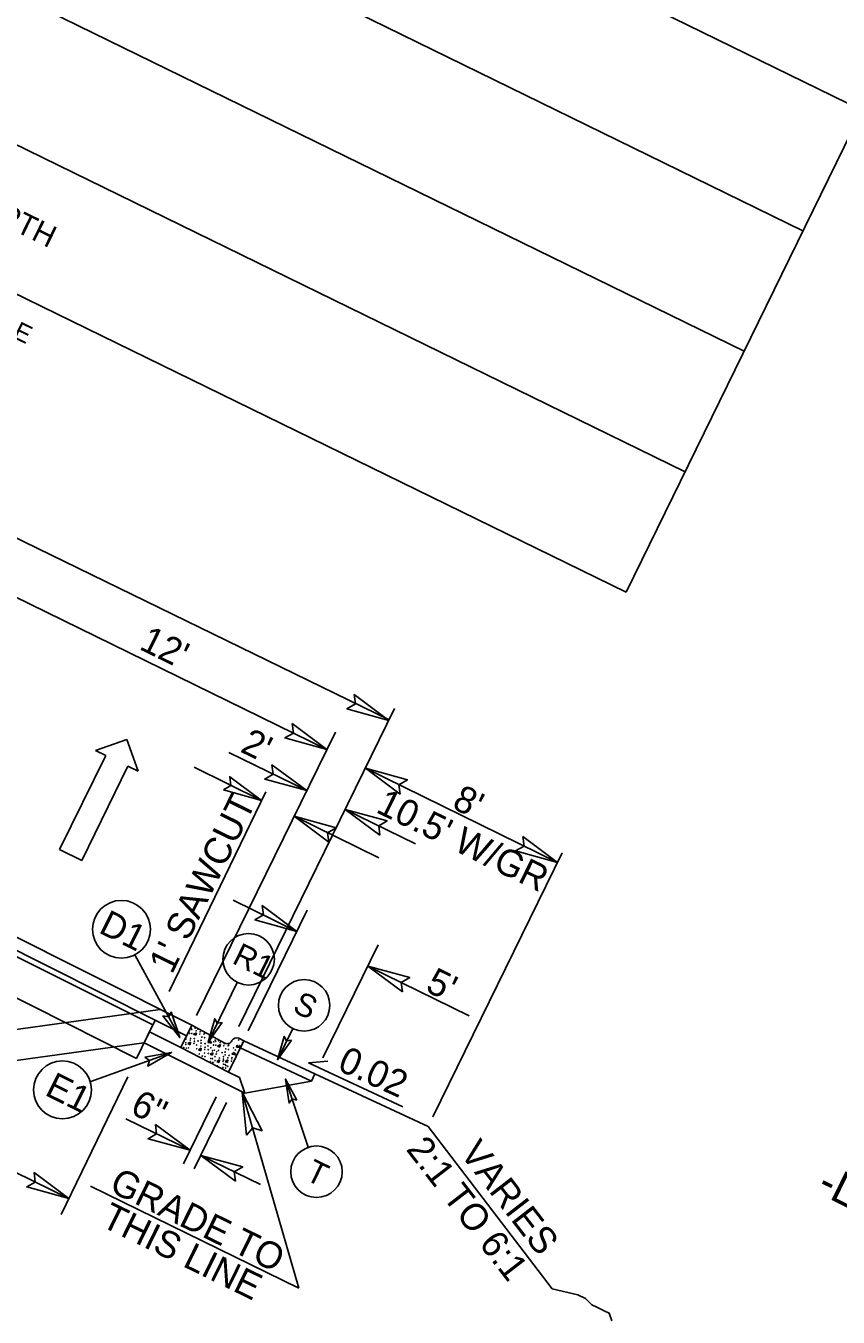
# Model space of a CAD drawing. Extents: x 1518247 to 1523638, y 635234 to 639927.
# Drawn here: x 1521902.2 to 1522204.9, y 638576.7 to 639057.9 of the extents above; entities that cross this region are included whole.
import ezdxf

# ---------------------------------------------------------------- set-up
doc = ezdxf.new("R2010")
doc.units = 0
for name, color, linetype in [('DTM TIN Hull White', 7, 'Continuous'), ('Old_Level_21', 7, 'Continuous'), ('Prop Dimension', 7, 'Continuous'), ('Prop Lane Arrow CELL', 7, 'Continuous'), ('Prop Shade Light', 7, 'Continuous'), ('Sheet Typical CELL', 7, 'Continuous'), ('Typical Arrow Superelevation CELL', 7, 'Continuous'), ('Typical Berm CELL', 7, 'Continuous'), ('Typical Berm Information CELL', 7, 'Continuous'), ('Typical Curb CELL', 7, 'Continuous'), ('Typical Hinge Slope Arterial CELL', 7, 'Continuous'), ('Typical Hinge Slope Interstate CELL', 7, 'Continuous'), ('Typical ID Circle CELL', 7, 'Continuous'), ('Typical Pavement Slope CELL', 7, 'Continuous'), ('Typical Text General CELL', 7, 'Continuous'), ('Typical Text ID Circle CELL', 7, 'Continuous')]:
    doc.layers.add(name, color=color, linetype=linetype)

# ---------------------------------------------------------------- blocks, each defined once
blk = doc.blocks.new('TERMINATOR')
at = {"layer": 'Prop Shade Light'}
blk.add_lwpolyline([(-0.469, 0.081), (0, 0), (-0.471, -0.083), (-0.411, 0)], close=True, dxfattribs=at)

msp = doc.modelspace()

# ---------------------------------------------------------------- linework, layer by layer
at = {"layer": 'DTM TIN Hull White'}
for p, q in [((1521949.57, 638685.65), (1521767.55, 638776.75)), ((1521943.46, 638673.16), (1521761.27, 638764.74)), ((1521949.57, 638685.65), (1521943.46, 638673.16))]:
    msp.add_line(p, q, dxfattribs=at)
at = {"layer": 'Prop Dimension'}
for p, q in [((1522037.58, 638799.28), (1521619.64, 639003.32)), ((1521819.91, 638883.5), (1522014.4, 638788.21)), ((1521981.59, 638685.01), (1522039.67, 638803.53)), ((1521918.24, 638620.97), (1521552.58, 638799.48)), ((1521965.84, 638689.11), (1522017.62, 638794.78)), ((1521977.9, 638787.19), (1522006.91, 638772.98)), ((1521964.93, 638781.64), (1521990.11, 638769.3)), ((1522028.76, 638781.27), (1522100.35, 638746.19)), ((1521955.64, 638698.1), (1521991.67, 638772.52)), ((1522002.22, 638763.37), (1522033.82, 638747.89)), ((1522021.23, 638765.96), (1522047.38, 638753.15)), ((1522053.91, 638651.42), (1522102.1, 638749.77)), ((1521979.52, 638732.12), (1522003.25, 638720.49)), ((1521985.11, 638683.47), (1522007.12, 638728.37)), ((1522012.86, 638673.35), (1522033.49, 638715.45)), ((1522029.63, 638707.57), (1522067.44, 638689.04)), ((1521952.32, 638691.4), (1521882.21, 638681.7)), ((1521946.26, 638678.93), (1521876.19, 638669.24)), ((1521915.38, 638614.96), (1521940.23, 638666.29)), ((1522004.01, 638587.52), (1521982.89, 638660.63)), ((1521973.18, 638658.79), (1521960.98, 638633.88)), ((1521977.05, 638656.67), (1521964.98, 638632.03)), ((1521939.47, 638650.69), (1521963.46, 638638.94)), ((1521967.41, 638637), (1521989.64, 638626.11)), ((1521926.38, 638625.56), (1522004.01, 638587.52))]:
    msp.add_line(p, q, dxfattribs=at)
at = {"layer": 'Prop Lane Arrow CELL'}
for p, q in [((1521928.25, 638787.93), (1521939.89, 638792.02)), ((1521939.89, 638792.02), (1521944.05, 638780.19)), ((1521914.82, 638751), (1521932.01, 638786.09)), ((1521932.01, 638786.09), (1521928.25, 638787.93)), ((1521940.29, 638782.04), (1521923.09, 638746.94)), ((1521944.05, 638780.19), (1521940.29, 638782.04)), ((1521923.09, 638746.94), (1521914.82, 638751))]:
    msp.add_line(p, q, dxfattribs=at)
at = {"layer": 'Prop Shade Light'}
for points in [[(1521956.41, 638690.56), (1521959.59, 638680.94), (1521953.3, 638688.97), (1521955.47, 638688.68)], [(1521975.41, 638686.54), (1521970.13, 638679.24), (1521972.64, 638687.95), (1521973.56, 638686.24)], [(1522001.27, 638679.97), (1521996, 638672.67), (1521998.51, 638681.38), (1521999.42, 638679.67)], [(1521946.55, 638673.62), (1521956.53, 638675.36), (1521947.67, 638670.31), (1521948.27, 638672.41)], [(1522003.26, 638657.54), (1521999, 638665.48), (1522000.33, 638656.51), (1522001.47, 638658.08)]]:
    msp.add_lwpolyline(points, close=True, dxfattribs=at)
at = {"layer": 'Sheet Typical CELL'}
for p, q in [((1522125.92, 638846.87), (1522393.92, 639394.84)), ((1521704.98, 639275.38), (1522213.79, 639026.53)), ((1521683.02, 639230.46), (1522191.82, 638981.61)), ((1521661.05, 639185.55), (1522169.86, 638936.7)), ((1521639.08, 639140.63), (1522147.89, 638891.78)), ((1521617.12, 639095.71), (1522125.92, 638846.87)), ((1522008.69, 638664.72), (1521982.13, 638677.05))]:
    msp.add_line(p, q, dxfattribs=at)
at = {"layer": 'Typical Arrow Superelevation CELL'}
msp.add_line((1522007.51, 638671.46), (1522014.77, 638672.1), dxfattribs=at)
at = {"layer": 'Typical Berm CELL'}
msp.add_line((1522052.16, 638647.84), (1521983.45, 638679.75), dxfattribs=at)
at = {"layer": 'Typical Berm Information CELL'}
msp.add_line((1522007.51, 638671.46), (1522042.73, 638655.1), dxfattribs=at)
at = {"layer": 'Typical Curb CELL'}
for p, q in [((1521960, 638677.18), (1521964.09, 638685.53)), ((1521964.09, 638685.53), (1521976.37, 638678.87)), ((1521964.75, 638682.16), (1521965.79, 638682.71)), ((1521965.64, 638681.78), (1521964.75, 638682.16)), ((1521965.79, 638682.71), (1521965.64, 638681.78)), ((1521970.05, 638679.11), (1521970.9, 638679.71)), ((1521970.9, 638679.71), (1521971.38, 638678.81)), ((1521977.72, 638668.05), (1521983.45, 638679.75)), ((1521979, 638679.71), (1521979.03, 638679.78)), ((1521983.45, 638679.75), (1521981.59, 638680.66)), ((1521977.72, 638668.05), (1521960, 638677.18)), ((1521962.57, 638678.65), (1521963.61, 638679.2)), ((1521963.46, 638678.27), (1521962.57, 638678.65)), ((1521963.61, 638679.2), (1521963.46, 638678.27)), ((1521966.55, 638676.4), (1521967.59, 638676.96)), ((1521967.44, 638676.03), (1521966.55, 638676.4)), ((1521967.59, 638676.96), (1521967.44, 638676.03)), ((1521971.38, 638678.81), (1521970.05, 638679.11)), ((1521970.88, 638674.7), (1521971.92, 638675.25)), ((1521971.92, 638675.25), (1521971.76, 638674.32)), ((1521973.7, 638677.77), (1521974.73, 638678.33)), ((1521974.58, 638677.4), (1521973.7, 638677.77)), ((1521974.73, 638678.33), (1521974.58, 638677.4)), ((1521978.99, 638674.72), (1521979.84, 638675.33)), ((1521979.84, 638675.33), (1521980.32, 638674.43)), ((1521980.92, 638678.03), (1521980.72, 638677.32)), ((1521980.72, 638677.32), (1521981.87, 638677.17)), ((1521981.87, 638677.17), (1521980.92, 638678.03)), ((1521971.76, 638674.32), (1521970.88, 638674.7)), ((1521973.39, 638672.01), (1521974.43, 638672.57)), ((1521974.28, 638671.63), (1521973.39, 638672.01)), ((1521974.43, 638672.57), (1521974.28, 638671.63)), ((1521976.53, 638672.05), (1521977.57, 638672.61)), ((1521977.42, 638671.68), (1521976.53, 638672.05)), ((1521977.57, 638672.61), (1521977.42, 638671.68)), ((1521980.32, 638674.43), (1521978.99, 638674.72))]:
    msp.add_line(p, q, dxfattribs=at)
for centre in [(1521965.3, 638684.42), (1521961.91, 638680.39), (1521962.22, 638681.52), (1521963.25, 638682.49), (1521963.35, 638683.71), (1521963.52, 638679.96), (1521963.65, 638680.62), (1521963.81, 638684.35), (1521964.09, 638683.91), (1521964.1, 638682.48), (1521965.03, 638680.55), (1521965.7, 638683.47), (1521966.38, 638684.04), (1521966.42, 638679.67), (1521967.07, 638682.24), (1521967.23, 638683.07), (1521967.54, 638679.88), (1521967.84, 638681.1), (1521968.64, 638682.23), (1521968.84, 638680.87), (1521968.94, 638682.53), (1521970.68, 638681.43), (1521971.36, 638680.64), (1521972.75, 638679.96), (1521974.1, 638679.73), (1521981.54, 638680.01), (1521961.06, 638677.22), (1521961.87, 638678.35), (1521961.92, 638678.97), (1521962.06, 638676.98), (1521962.85, 638677.04), (1521964.9, 638678.73), (1521965.05, 638679.56), (1521965.89, 638678.15), (1521965.9, 638676.73), (1521966.83, 638674.8), (1521967.5, 638677.72), (1521967.55, 638678.86), (1521968.8, 638675.16), (1521968.88, 638676.49), (1521969.04, 638678.69), (1521969.03, 638677.31), (1521970.12, 638677.8), (1521970.22, 638676.45), (1521970.23, 638675.02), (1521971.17, 638677.14), (1521971.83, 638676.01), (1521972.2, 638678.11), (1521972.29, 638679.33), (1521972.59, 638676.24), (1521973.03, 638679.52), (1521973.05, 638678.1), (1521973.36, 638675.61), (1521973.98, 638676.17), (1521974.64, 638679.09), (1521975.37, 638675.29), (1521976.02, 638677.86), (1521976.17, 638678.68), (1521976.49, 638675.5), (1521976.78, 638676.72), (1521977.59, 638677.85), (1521977.78, 638676.48), (1521977.89, 638678.15), (1521979.63, 638677.04), (1521980.31, 638676.26), (1521981.96, 638677.88), (1521982.97, 638679), (1521967.99, 638674.03), (1521968.99, 638673.8), (1521970.95, 638671.92), (1521971.16, 638673.1), (1521971.76, 638673.04), (1521971.95, 638671.68), (1521972.73, 638673.76), (1521972.74, 638672.33), (1521973.2, 638674.78), (1521973.67, 638670.41), (1521974.34, 638673.32), (1521975.72, 638672.09), (1521975.87, 638673.8), (1521975.87, 638672.92), (1521975.88, 638672.38), (1521975.91, 638670.98), (1521976.5, 638674.48), (1521976.51, 638670.93), (1521976.82, 638670.45), (1521977.48, 638673.37), (1521977.49, 638670.22), (1521977.98, 638674.31), (1521978.86, 638672.14), (1521979.01, 638672.96), (1521979.07, 638673.42), (1521975.7, 638669.8), (1521976.7, 638669.56)]:
    msp.add_circle(centre, 0.064, dxfattribs=at)
for centre, start, end in [((1521977.28, 638680.55), 241.5117, 333.8962), ((1521980.75, 638678.94), 63.8962, 153.8962)]:
    msp.add_arc(centre, 1.91, start, end, dxfattribs=at)
at = {"layer": 'Typical Hinge Slope Interstate CELL'}
for p, q in [((1522009.98, 638667.43), (1522008.69, 638664.72)), ((1522052.16, 638647.84), (1522098.38, 638587.23))]:
    msp.add_line(p, q, dxfattribs=at)
msp.add_lwpolyline([(1522098.38, 638587.23), (1522107.98, 638585.02), (1522110.77, 638583.66), (1522113.1, 638581.37), (1522114.95, 638580.46), (1522117.74, 638579.09), (1522119.6, 638578.18), (1522120.54, 638575.41)], dxfattribs=at)
at = {"layer": 'Typical ID Circle CELL'}
for p, q in [((1521959.24, 638681.65), (1521942.86, 638711.7)), ((1521981.03, 638701.49), (1521970.13, 638679.24)), ((1522001.7, 638684.32), (1521996, 638672.67)), ((1521926.5, 638664.56), (1521956.55, 638675.35)), ((1522007.49, 638640.02), (1521999, 638665.48))]:
    msp.add_line(p, q, dxfattribs=at)
for centre, radius in [((1521937.87, 638721.26), 10.78), ((1521985.25, 638710.1), 9.59), ((1522005.92, 638692.93), 9.59), ((1521915.89, 638661.42), 10.78), ((1522010.53, 638630.93), 9.59)]:
    msp.add_circle(centre, radius, dxfattribs=at)
at = {"layer": 'Typical Pavement Slope CELL'}
for p, q in [((1521770.4, 638782.47), (1521964.09, 638685.53)), ((1521950.42, 638687.37), (1521768.58, 638778.92)), ((1521950.42, 638687.37), (1521946.3, 638678.94)), ((1521962.07, 638681.54), (1521950.42, 638687.37)), ((1521960, 638677.18), (1521948.34, 638683.01)), ((1521983.82, 638660.16), (1521946.3, 638678.94)), ((1521977.72, 638668.05), (1521981.81, 638666.04)), ((1521981.81, 638666.04), (1521983.82, 638660.16)), ((1521983.82, 638660.16), (1522008.69, 638664.72))]:
    msp.add_line(p, q, dxfattribs=at)

# ---------------------------------------------------------------- block references
at = {"layer": 'Prop Dimension'}
for p, xscale, yscale, rotation in [((1522037.51, 638799.13), 33.82820784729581, 36.4155251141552, -26.103820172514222), ((1522014.44, 638788.29), 33.82820784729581, 36.4155251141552, -26.103820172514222), ((1522006.91, 638772.98), 33.82820784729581, 36.4155251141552, -26.103820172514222), ((1522028.76, 638781.27), 33.82820784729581, 36.4155251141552, 153.89617982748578), ((1521990.11, 638769.3), 30.938856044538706, -33.30518407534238, -25.836011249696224), ((1522021.23, 638765.96), 33.82820784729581, 36.4155251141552, 153.89617982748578), ((1522002.22, 638763.37), 33.82820784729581, 36.4155251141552, 153.89617982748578), ((1522100.35, 638746.19), 33.82820784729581, 36.4155251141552, -26.103820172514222), ((1522003.25, 638720.49), 33.82820784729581, 36.4155251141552, -26.103820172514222), ((1522029.63, 638707.57), 33.82820784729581, 36.4155251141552, 153.89617982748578), ((1521982.89, 638660.63), 33.828207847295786, 36.415525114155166, 106.22234335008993), ((1521963.46, 638638.94), 33.82820784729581, 36.4155251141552, -26.103820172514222), ((1521967.41, 638637), 33.82820784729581, 36.4155251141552, 153.89617982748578), ((1521918.24, 638620.97), 33.82820784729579, 36.41552511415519, -26.103820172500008)]:
    msp.add_blockref('TERMINATOR', p, dxfattribs=dict(at, xscale=xscale, yscale=yscale, rotation=rotation))

# ---------------------------------------------------------------- texts
at = {"layer": 'Old_Level_21'}
msp.add_text('NOTE:  PAVEMENT EDGE SLOPES ARE 1:1 UNLESS SHOWN OTHERWISE', height=6.75, rotation=333.8298, dxfattribs=at).set_placement((1521617.01, 639079.5))
at = {"layer": 'Prop Dimension'}
for s, height, rotation, p in [("12'", 9.969, 333.8962, (1521944.1, 638825.83)), ("2'", 9.969, 333.9793, (1521981.76, 638787.61)), ("1' SAWCUT", 10, 63.9377, (1521956.69, 638704.2)), ("10.5' W/GR", 9.969, 333.8962, (1522032.27, 638765.07)), ("8'", 9.969, 333.8962, (1522060.61, 638766.59)), ("5'", 9.969, 333.9793, (1522050.7, 638698.41)), ('6"', 9.969, 333.8962, (1521940.68, 638652.91))]:
    msp.add_text(s, height=height, rotation=rotation, dxfattribs=at).set_placement(p)
at = {"layer": 'Sheet Typical CELL'}
msp.add_text('MILLING BITUMINOUS PAVEMENT. 1 1/2" DEPTH', height=8.1788, rotation=333.8298, dxfattribs=at).set_placement((1521683.86, 639086.68))
at = {"layer": 'Typical Berm Information CELL'}
msp.add_text('0.02', height=9.969, rotation=335.7046, dxfattribs=at).set_placement((1522017.92, 638668.95))
at = {"layer": 'Typical Hinge Slope Arterial CELL'}
for s, p in [('2:1 TO 6:1', (1522043.65, 638639.21)), ('VARIES', (1522063.66, 638637.77))]:
    msp.add_text(s, height=9.969, rotation=307.6683, dxfattribs=at).set_placement(p)
at = {"layer": 'Typical Pavement Slope CELL'}
msp.add_text('-L- STA. 25+35.00 to -L- STA. 25+85.00', height=11.8983, rotation=333.8962, dxfattribs=at).set_placement((1522196.49, 638623.31))
at = {"layer": 'Typical Text General CELL'}
for s, p in [('GRADE TO', (1521932.87, 638623.86)), ('THIS LINE', (1521929.73, 638610.85))]:
    msp.add_text(s, height=9.969, rotation=333.8962, dxfattribs=at).set_placement(p)
at = {"layer": 'Typical Text ID Circle CELL'}
for s, height, rotation, p in [('D1', 9.65, 333.6189, (1521928.98, 638720.18)), ('R1', 8.581, 333.8962, (1521978.69, 638708.8)), ('S', 8.58, 333.9793, (1522001.2, 638690.77)), ('E1', 9.65, 333.6189, (1521908.92, 638659.69)), ('T', 8.58, 333.8962, (1522005.9, 638628.17))]:
    msp.add_text(s, height=height, rotation=rotation, dxfattribs=at).set_placement(p)

doc.saveas('drawing.dxf')
